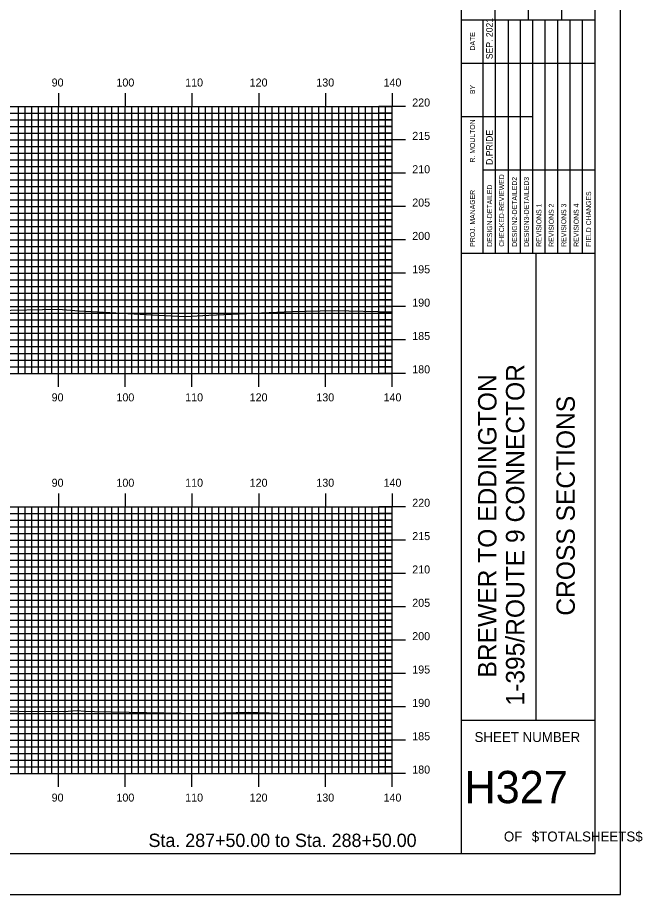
# Model space of a CAD drawing. Extents: x 1812948 to 1813291, y 442591 to 442811.
# Drawn here: x 1813197.3 to 1813291, y 442590.5 to 442722 of the extents above; entities that cross this region are included whole.
import ezdxf

# ---------------------------------------------------------------- set-up
doc = ezdxf.new("R2010")
doc.units = 0
for name, color, linetype in [('BORDER', 7, 'Continuous'), ('H_V ANNOTATION', 7, 'Continuous'), ('MAJOR', 7, 'Continuous'), ('MINOR', 7, 'Continuous'), ('PLOT BOUNDARY', 7, 'Continuous'), ('S_Roadway_Centerline', 7, 'Continuous')]:
    doc.layers.add(name, color=color, linetype=linetype)

msp = doc.modelspace()

# ---------------------------------------------------------------- linework, layer by layer
at = {"layer": 'BORDER'}
for p, q in [((1813263.86, 442596.67), (1813263.86, 442806.67)), ((1813268.86, 442721.67), (1813268.86, 442738.97)), ((1813273.86, 442721.67), (1813273.86, 442738.97)), ((1813278.86, 442721.67), (1813278.86, 442738.97)), ((1813263.86, 442721.67), (1813283.86, 442721.67)), ((1813263.86, 442686.67), (1813283.86, 442686.67)), ((1813275.04, 442616.67), (1813275.04, 442686.67)), ((1813263.86, 442616.67), (1813283.86, 442616.67))]:
    msp.add_line(p, q, dxfattribs=at)
msp.add_lwpolyline([(1812963.86, 442596.67), (1813283.86, 442596.67), (1813283.86, 442806.67), (1812963.86, 442806.67)], close=True, dxfattribs=at)
for points in [[(1813267.08, 442715.17), (1813267.08, 442721.67)], [(1813268.95, 442686.68), (1813268.95, 442721.67)], [(1813270.81, 442721.67), (1813270.81, 442686.68)], [(1813272.68, 442686.68), (1813272.68, 442721.67)], [(1813274.54, 442686.68), (1813274.54, 442721.67)], [(1813276.4, 442686.68), (1813276.4, 442721.67)], [(1813278.27, 442686.68), (1813278.27, 442721.67)], [(1813280.13, 442686.68), (1813280.13, 442721.67)], [(1813281.99, 442686.68), (1813281.99, 442721.67)], [(1813267.09, 442686.68), (1813267.09, 442720.26)], [(1813263.86, 442715.17), (1813283.86, 442715.17)], [(1813263.86, 442707.17), (1813267.09, 442707.17)], [(1813267.08, 442707.17), (1813274.54, 442707.17)], [(1813267.08, 442699.17), (1813283.86, 442699.17)]]:
    msp.add_lwpolyline(points, dxfattribs=at)
at = {"layer": 'MAJOR'}
for p, q in [((1813203.46, 442710.67), (1813203.46, 442708.67)), ((1813213.46, 442710.67), (1813213.46, 442708.67)), ((1813223.46, 442710.67), (1813223.46, 442708.67)), ((1813233.46, 442710.67), (1813233.46, 442708.67)), ((1813243.46, 442710.67), (1813243.46, 442708.67)), ((1813253.46, 442710.67), (1813253.46, 442708.67)), ((1812973.46, 442708.67), (1813253.46, 442708.67)), ((1812973.46, 442708.67), (1813253.46, 442708.67)), ((1813203.46, 442668.67), (1813203.46, 442708.67)), ((1813213.46, 442668.67), (1813213.46, 442708.67)), ((1813223.46, 442668.67), (1813223.46, 442708.67)), ((1813233.46, 442668.67), (1813233.46, 442708.67)), ((1813243.46, 442668.67), (1813243.46, 442708.67)), ((1813255.46, 442708.67), (1813251.45, 442708.67)), ((1813253.46, 442668.67), (1813253.46, 442708.67)), ((1813253.46, 442668.67), (1813253.46, 442708.67)), ((1812973.46, 442703.67), (1813253.46, 442703.67)), ((1813255.46, 442703.67), (1813251.45, 442703.67)), ((1812973.46, 442698.67), (1813253.46, 442698.67)), ((1813255.46, 442698.67), (1813251.45, 442698.67)), ((1812973.46, 442693.67), (1813253.46, 442693.67)), ((1813255.46, 442693.67), (1813251.45, 442693.67)), ((1812973.46, 442688.67), (1813253.46, 442688.67)), ((1813255.46, 442688.67), (1813251.45, 442688.67)), ((1812973.46, 442683.67), (1813253.46, 442683.67)), ((1813255.46, 442683.67), (1813251.45, 442683.67)), ((1812973.46, 442678.67), (1813253.46, 442678.67)), ((1813255.46, 442678.67), (1813251.45, 442678.67)), ((1812973.46, 442673.67), (1813253.46, 442673.67)), ((1813255.46, 442673.67), (1813251.45, 442673.67)), ((1812973.46, 442668.67), (1813253.46, 442668.67)), ((1812973.46, 442668.67), (1813253.46, 442668.67)), ((1813203.46, 442666.66), (1813203.46, 442668.67)), ((1813213.46, 442666.66), (1813213.46, 442668.67)), ((1813223.46, 442666.66), (1813223.46, 442668.67)), ((1813233.46, 442666.66), (1813233.46, 442668.67)), ((1813243.46, 442666.66), (1813243.46, 442668.67)), ((1813255.46, 442668.67), (1813251.45, 442668.67)), ((1813253.46, 442666.66), (1813253.46, 442668.67)), ((1813203.46, 442650.67), (1813203.46, 442648.67)), ((1813213.46, 442650.67), (1813213.46, 442648.67)), ((1813223.46, 442650.67), (1813223.46, 442648.67)), ((1813233.46, 442650.67), (1813233.46, 442648.67)), ((1813243.46, 442650.67), (1813243.46, 442648.67)), ((1813253.46, 442650.67), (1813253.46, 442648.67)), ((1812973.46, 442648.67), (1813253.46, 442648.67)), ((1812973.46, 442648.67), (1813253.46, 442648.67)), ((1813203.46, 442608.67), (1813203.46, 442648.67)), ((1813213.46, 442608.67), (1813213.46, 442648.67)), ((1813223.46, 442608.67), (1813223.46, 442648.67)), ((1813233.46, 442608.67), (1813233.46, 442648.67)), ((1813243.46, 442608.67), (1813243.46, 442648.67)), ((1813255.46, 442648.67), (1813251.45, 442648.67)), ((1813253.46, 442608.67), (1813253.46, 442648.67)), ((1813253.46, 442608.67), (1813253.46, 442648.67)), ((1812973.46, 442643.67), (1813253.46, 442643.67)), ((1813255.46, 442643.67), (1813251.45, 442643.67)), ((1812973.46, 442638.67), (1813253.46, 442638.67)), ((1813255.46, 442638.67), (1813251.45, 442638.67)), ((1812973.46, 442633.67), (1813253.46, 442633.67)), ((1813255.46, 442633.67), (1813251.45, 442633.67)), ((1812973.46, 442628.67), (1813253.46, 442628.67)), ((1813255.46, 442628.67), (1813251.45, 442628.67)), ((1812973.46, 442623.67), (1813253.46, 442623.67)), ((1813255.46, 442623.67), (1813251.45, 442623.67)), ((1812973.46, 442618.67), (1813253.46, 442618.67)), ((1813255.46, 442618.67), (1813251.45, 442618.67)), ((1812973.46, 442613.67), (1813253.46, 442613.67)), ((1813255.46, 442613.67), (1813251.45, 442613.67)), ((1812973.46, 442608.67), (1813253.46, 442608.67)), ((1812973.46, 442608.67), (1813253.46, 442608.67)), ((1813203.46, 442606.66), (1813203.46, 442608.67)), ((1813213.46, 442606.66), (1813213.46, 442608.67)), ((1813223.46, 442606.66), (1813223.46, 442608.67)), ((1813233.46, 442606.66), (1813233.46, 442608.67)), ((1813243.46, 442606.66), (1813243.46, 442608.67)), ((1813255.46, 442608.67), (1813251.45, 442608.67)), ((1813253.46, 442606.66), (1813253.46, 442608.67))]:
    msp.add_line(p, q, dxfattribs=at)
at = {"layer": 'MINOR'}
for p, q in [((1813197.46, 442668.67), (1813197.46, 442708.67)), ((1813198.46, 442668.67), (1813198.46, 442708.67)), ((1813199.46, 442668.67), (1813199.46, 442708.67)), ((1813200.46, 442668.67), (1813200.46, 442708.67)), ((1813201.46, 442668.67), (1813201.46, 442708.67)), ((1813202.46, 442668.67), (1813202.46, 442708.67)), ((1813204.46, 442668.67), (1813204.46, 442708.67)), ((1813205.46, 442668.67), (1813205.46, 442708.67)), ((1813206.46, 442668.67), (1813206.46, 442708.67)), ((1813207.46, 442668.67), (1813207.46, 442708.67)), ((1813208.46, 442668.67), (1813208.46, 442708.67)), ((1813209.46, 442668.67), (1813209.46, 442708.67)), ((1813210.46, 442668.67), (1813210.46, 442708.67)), ((1813211.46, 442668.67), (1813211.46, 442708.67)), ((1813212.46, 442668.67), (1813212.46, 442708.67)), ((1813214.46, 442668.67), (1813214.46, 442708.67)), ((1813215.46, 442668.67), (1813215.46, 442708.67)), ((1813216.46, 442668.67), (1813216.46, 442708.67)), ((1813217.46, 442668.67), (1813217.46, 442708.67)), ((1813218.46, 442668.67), (1813218.46, 442708.67)), ((1813219.46, 442668.67), (1813219.46, 442708.67)), ((1813220.46, 442668.67), (1813220.46, 442708.67)), ((1813221.46, 442668.67), (1813221.46, 442708.67)), ((1813222.46, 442668.67), (1813222.46, 442708.67)), ((1813224.46, 442668.67), (1813224.46, 442708.67)), ((1813225.46, 442668.67), (1813225.46, 442708.67)), ((1813226.46, 442668.67), (1813226.46, 442708.67)), ((1813227.46, 442668.67), (1813227.46, 442708.67)), ((1813228.46, 442668.67), (1813228.46, 442708.67)), ((1813229.46, 442668.67), (1813229.46, 442708.67)), ((1813230.46, 442668.67), (1813230.46, 442708.67)), ((1813231.46, 442668.67), (1813231.46, 442708.67)), ((1813232.46, 442668.67), (1813232.46, 442708.67)), ((1813234.46, 442668.67), (1813234.46, 442708.67)), ((1813235.46, 442668.67), (1813235.46, 442708.67)), ((1813236.46, 442668.67), (1813236.46, 442708.67)), ((1813237.46, 442668.67), (1813237.46, 442708.67)), ((1813238.46, 442668.67), (1813238.46, 442708.67)), ((1813239.46, 442668.67), (1813239.46, 442708.67)), ((1813240.46, 442668.67), (1813240.46, 442708.67)), ((1813241.46, 442668.67), (1813241.46, 442708.67)), ((1813242.46, 442668.67), (1813242.46, 442708.67)), ((1813244.46, 442668.67), (1813244.46, 442708.67)), ((1813245.46, 442668.67), (1813245.46, 442708.67)), ((1813246.46, 442668.67), (1813246.46, 442708.67)), ((1813247.46, 442668.67), (1813247.46, 442708.67)), ((1813248.46, 442668.67), (1813248.46, 442708.67)), ((1813249.46, 442668.67), (1813249.46, 442708.67)), ((1813250.46, 442668.67), (1813250.46, 442708.67)), ((1813251.46, 442668.67), (1813251.46, 442708.67)), ((1813252.46, 442668.67), (1813252.46, 442708.67)), ((1812973.46, 442707.67), (1813253.46, 442707.67)), ((1813253.46, 442707.67), (1813251.45, 442707.67)), ((1812973.46, 442706.67), (1813253.46, 442706.67)), ((1812973.46, 442705.67), (1813253.46, 442705.67)), ((1813253.46, 442706.67), (1813251.45, 442706.67)), ((1813253.46, 442705.67), (1813251.45, 442705.67)), ((1812973.46, 442704.67), (1813253.46, 442704.67)), ((1813253.46, 442704.67), (1813251.45, 442704.67)), ((1812973.46, 442702.67), (1813253.46, 442702.67)), ((1812973.46, 442701.67), (1813253.46, 442701.67)), ((1813253.46, 442702.67), (1813251.45, 442702.67)), ((1813253.46, 442701.67), (1813251.45, 442701.67)), ((1812973.46, 442700.67), (1813253.46, 442700.67)), ((1813253.46, 442700.67), (1813251.45, 442700.67)), ((1812973.46, 442699.67), (1813253.46, 442699.67)), ((1813253.46, 442699.67), (1813251.45, 442699.67)), ((1812973.46, 442697.67), (1813253.46, 442697.67)), ((1813253.46, 442697.67), (1813251.45, 442697.67)), ((1812973.46, 442696.67), (1813253.46, 442696.67)), ((1813253.46, 442696.67), (1813251.45, 442696.67)), ((1812973.46, 442695.67), (1813253.46, 442695.67)), ((1813253.46, 442695.67), (1813251.45, 442695.67)), ((1812973.46, 442694.67), (1813253.46, 442694.67)), ((1813253.46, 442694.67), (1813251.45, 442694.67)), ((1812973.46, 442692.67), (1813253.46, 442692.67)), ((1813253.46, 442692.67), (1813251.45, 442692.67)), ((1812973.46, 442691.67), (1813253.46, 442691.67)), ((1813253.46, 442691.67), (1813251.45, 442691.67)), ((1812973.46, 442690.67), (1813253.46, 442690.67)), ((1813253.46, 442690.67), (1813251.45, 442690.67)), ((1812973.46, 442689.67), (1813253.46, 442689.67)), ((1813253.46, 442689.67), (1813251.45, 442689.67)), ((1812973.46, 442687.67), (1813253.46, 442687.67)), ((1813253.46, 442687.67), (1813251.45, 442687.67)), ((1812973.46, 442686.67), (1813253.46, 442686.67)), ((1813253.46, 442686.67), (1813251.45, 442686.67)), ((1812973.46, 442685.67), (1813253.46, 442685.67)), ((1812973.46, 442684.67), (1813253.46, 442684.67)), ((1813253.46, 442685.67), (1813251.45, 442685.67)), ((1813253.46, 442684.67), (1813251.45, 442684.67)), ((1812973.46, 442682.67), (1813253.46, 442682.67)), ((1813253.46, 442682.67), (1813251.45, 442682.67)), ((1812973.46, 442681.67), (1813253.46, 442681.67)), ((1812973.46, 442680.67), (1813253.46, 442680.67)), ((1813253.46, 442681.67), (1813251.45, 442681.67)), ((1813253.46, 442680.67), (1813251.45, 442680.67)), ((1812973.46, 442679.67), (1813253.46, 442679.67)), ((1813253.46, 442679.67), (1813251.45, 442679.67)), ((1812973.46, 442677.67), (1813253.46, 442677.67)), ((1812973.46, 442676.67), (1813253.46, 442676.67)), ((1813253.46, 442677.67), (1813251.45, 442677.67)), ((1813253.46, 442676.67), (1813251.45, 442676.67)), ((1812973.46, 442675.67), (1813253.46, 442675.67)), ((1813253.46, 442675.67), (1813251.45, 442675.67)), ((1812973.46, 442674.67), (1813253.46, 442674.67)), ((1813253.46, 442674.67), (1813251.45, 442674.67)), ((1812973.46, 442672.67), (1813253.46, 442672.67)), ((1813253.46, 442672.67), (1813251.45, 442672.67)), ((1812973.46, 442671.67), (1813253.46, 442671.67)), ((1813253.46, 442671.67), (1813251.45, 442671.67)), ((1812973.46, 442670.67), (1813253.46, 442670.67)), ((1813253.46, 442670.67), (1813251.45, 442670.67)), ((1812973.46, 442669.67), (1813253.46, 442669.67)), ((1813253.46, 442669.67), (1813251.45, 442669.67)), ((1812973.46, 442647.67), (1813253.46, 442647.67)), ((1813197.46, 442608.67), (1813197.46, 442648.67)), ((1813198.46, 442608.67), (1813198.46, 442648.67)), ((1813199.46, 442608.67), (1813199.46, 442648.67)), ((1813200.46, 442608.67), (1813200.46, 442648.67)), ((1813201.46, 442608.67), (1813201.46, 442648.67)), ((1813202.46, 442608.67), (1813202.46, 442648.67)), ((1813204.46, 442608.67), (1813204.46, 442648.67)), ((1813205.46, 442608.67), (1813205.46, 442648.67)), ((1813206.46, 442608.67), (1813206.46, 442648.67)), ((1813207.46, 442608.67), (1813207.46, 442648.67)), ((1813208.46, 442608.67), (1813208.46, 442648.67)), ((1813209.46, 442608.67), (1813209.46, 442648.67)), ((1813210.46, 442608.67), (1813210.46, 442648.67)), ((1813211.46, 442608.67), (1813211.46, 442648.67)), ((1813212.46, 442608.67), (1813212.46, 442648.67)), ((1813214.46, 442608.67), (1813214.46, 442648.67)), ((1813215.46, 442608.67), (1813215.46, 442648.67)), ((1813216.46, 442608.67), (1813216.46, 442648.67)), ((1813217.46, 442608.67), (1813217.46, 442648.67)), ((1813218.46, 442608.67), (1813218.46, 442648.67)), ((1813219.46, 442608.67), (1813219.46, 442648.67)), ((1813220.46, 442608.67), (1813220.46, 442648.67)), ((1813221.46, 442608.67), (1813221.46, 442648.67)), ((1813222.46, 442608.67), (1813222.46, 442648.67)), ((1813224.46, 442608.67), (1813224.46, 442648.67)), ((1813225.46, 442608.67), (1813225.46, 442648.67)), ((1813226.46, 442608.67), (1813226.46, 442648.67)), ((1813227.46, 442608.67), (1813227.46, 442648.67)), ((1813228.46, 442608.67), (1813228.46, 442648.67)), ((1813229.46, 442608.67), (1813229.46, 442648.67)), ((1813230.46, 442608.67), (1813230.46, 442648.67)), ((1813231.46, 442608.67), (1813231.46, 442648.67)), ((1813232.46, 442608.67), (1813232.46, 442648.67)), ((1813234.46, 442608.67), (1813234.46, 442648.67)), ((1813235.46, 442608.67), (1813235.46, 442648.67)), ((1813236.46, 442608.67), (1813236.46, 442648.67)), ((1813237.46, 442608.67), (1813237.46, 442648.67)), ((1813238.46, 442608.67), (1813238.46, 442648.67)), ((1813239.46, 442608.67), (1813239.46, 442648.67)), ((1813240.46, 442608.67), (1813240.46, 442648.67)), ((1813241.46, 442608.67), (1813241.46, 442648.67)), ((1813242.46, 442608.67), (1813242.46, 442648.67)), ((1813244.46, 442608.67), (1813244.46, 442648.67)), ((1813245.46, 442608.67), (1813245.46, 442648.67)), ((1813246.46, 442608.67), (1813246.46, 442648.67)), ((1813247.46, 442608.67), (1813247.46, 442648.67)), ((1813248.46, 442608.67), (1813248.46, 442648.67)), ((1813249.46, 442608.67), (1813249.46, 442648.67)), ((1813250.46, 442608.67), (1813250.46, 442648.67)), ((1813253.46, 442647.67), (1813251.45, 442647.67)), ((1813251.46, 442608.67), (1813251.46, 442648.67)), ((1813252.46, 442608.67), (1813252.46, 442648.67)), ((1812973.46, 442646.67), (1813253.46, 442646.67)), ((1813253.46, 442646.67), (1813251.45, 442646.67)), ((1812973.46, 442645.67), (1813253.46, 442645.67)), ((1813253.46, 442645.67), (1813251.45, 442645.67)), ((1812973.46, 442644.67), (1813253.46, 442644.67)), ((1813253.46, 442644.67), (1813251.45, 442644.67)), ((1812973.46, 442642.67), (1813253.46, 442642.67)), ((1813253.46, 442642.67), (1813251.45, 442642.67)), ((1812973.46, 442641.67), (1813253.46, 442641.67)), ((1813253.46, 442641.67), (1813251.45, 442641.67)), ((1812973.46, 442640.67), (1813253.46, 442640.67)), ((1813253.46, 442640.67), (1813251.45, 442640.67)), ((1812973.46, 442639.67), (1813253.46, 442639.67)), ((1813253.46, 442639.67), (1813251.45, 442639.67)), ((1812973.46, 442637.67), (1813253.46, 442637.67)), ((1813253.46, 442637.67), (1813251.45, 442637.67)), ((1812973.46, 442636.67), (1813253.46, 442636.67)), ((1813253.46, 442636.67), (1813251.45, 442636.67)), ((1812973.46, 442635.67), (1813253.46, 442635.67)), ((1812973.46, 442634.67), (1813253.46, 442634.67)), ((1813253.46, 442635.67), (1813251.45, 442635.67)), ((1813253.46, 442634.67), (1813251.45, 442634.67)), ((1812973.46, 442632.67), (1813253.46, 442632.67)), ((1813253.46, 442632.67), (1813251.45, 442632.67)), ((1812973.46, 442631.67), (1813253.46, 442631.67)), ((1812973.46, 442630.67), (1813253.46, 442630.67)), ((1813253.46, 442631.67), (1813251.45, 442631.67)), ((1813253.46, 442630.67), (1813251.45, 442630.67)), ((1812973.46, 442629.67), (1813253.46, 442629.67)), ((1813253.46, 442629.67), (1813251.45, 442629.67)), ((1812973.46, 442627.67), (1813253.46, 442627.67)), ((1812973.46, 442626.67), (1813253.46, 442626.67)), ((1813253.46, 442627.67), (1813251.45, 442627.67)), ((1813253.46, 442626.67), (1813251.45, 442626.67)), ((1812973.46, 442625.67), (1813253.46, 442625.67)), ((1813253.46, 442625.67), (1813251.45, 442625.67)), ((1812973.46, 442624.67), (1813253.46, 442624.67)), ((1813253.46, 442624.67), (1813251.45, 442624.67)), ((1812973.46, 442622.67), (1813253.46, 442622.67)), ((1813253.46, 442622.67), (1813251.45, 442622.67)), ((1812973.46, 442621.67), (1813253.46, 442621.67)), ((1813253.46, 442621.67), (1813251.45, 442621.67)), ((1812973.46, 442620.67), (1813253.46, 442620.67)), ((1813253.46, 442620.67), (1813251.45, 442620.67)), ((1812973.46, 442619.67), (1813253.46, 442619.67)), ((1813253.46, 442619.67), (1813251.45, 442619.67)), ((1812973.46, 442617.67), (1813253.46, 442617.67)), ((1813253.46, 442617.67), (1813251.45, 442617.67)), ((1812973.46, 442616.67), (1813253.46, 442616.67)), ((1813253.46, 442616.67), (1813251.45, 442616.67)), ((1812973.46, 442615.67), (1813253.46, 442615.67)), ((1813253.46, 442615.67), (1813251.45, 442615.67)), ((1812973.46, 442614.67), (1813253.46, 442614.67)), ((1813253.46, 442614.67), (1813251.45, 442614.67)), ((1812973.46, 442612.67), (1813253.46, 442612.67)), ((1813253.46, 442612.67), (1813251.45, 442612.67)), ((1812973.46, 442611.67), (1813253.46, 442611.67)), ((1813253.46, 442611.67), (1813251.45, 442611.67)), ((1812973.46, 442610.67), (1813253.46, 442610.67)), ((1812973.46, 442609.67), (1813253.46, 442609.67)), ((1813253.46, 442610.67), (1813251.45, 442610.67)), ((1813253.46, 442609.67), (1813251.45, 442609.67))]:
    msp.add_line(p, q, dxfattribs=at)
at = {"layer": 'PLOT BOUNDARY'}
msp.add_lwpolyline([(1812947.67, 442590.55), (1813287.67, 442590.55), (1813287.67, 442810.55), (1812947.67, 442810.55)], close=True, dxfattribs=at)
at = {"layer": 'S_Roadway_Centerline'}
for points in [[(1813193.92, 442678.09), (1813203.41, 442678.28), (1813206.56, 442678.02), (1813218.45, 442677.39), (1813222.46, 442677.19), (1813226, 442677.4), (1813238.43, 442677.95), (1813244.8, 442678.08), (1813253.46, 442677.88)], [(1813084.84, 442620.64), (1813088.36, 442620.5), (1813089.18, 442620.47), (1813090.73, 442620.43), (1813105.15, 442620.24), (1813112.48, 442620.04), (1813122.27, 442620.01), (1813139.78, 442619.7), (1813140.48, 442619.66), (1813141.1, 442619.66), (1813142.38, 442619.6), (1813168.45, 442618.61), (1813174.52, 442618.21), (1813185.03, 442618.05), (1813190.81, 442618.09), (1813204.22, 442618), (1813206.3, 442618.12), (1813207.36, 442618.02), (1813208.86, 442617.96), (1813224.42, 442617.68), (1813231.94, 442617.86), (1813241.21, 442617.57), (1813253.46, 442617.74)]]:
    msp.add_lwpolyline(points, dxfattribs=at)

# ---------------------------------------------------------------- texts
at = {"layer": 'BORDER'}
for s, height, p in [('SEP. 2021', 0.969, (1813268.5, 442715.76)), ('DATE', 0.743, (1813265.86, 442717.08)), ('BY', 0.743, (1813265.86, 442710.54)), ('R. MOULTON', 0.745, (1813265.86, 442700.28)), ('D.PRIDE', 0.969, (1813268.5, 442699.92)), ('CHECKED-REVIEWED', 0.7455, (1813270.22, 442687.65)), ('DESIGN2-DETAILED2', 0.7455, (1813272.16, 442687.65)), ('DESIGN3-DETAILED3', 0.7455, (1813273.94, 442687.65)), ('DESIGN-DETAILED', 0.7455, (1813268.43, 442687.65)), ('PROJ. MANAGER', 0.7455, (1813265.86, 442687.65)), ('FIELD CHANGES', 0.7455, (1813283.26, 442687.65)), ('REVISIONS 1', 0.7455, (1813275.81, 442687.65)), ('REVISIONS 2', 0.7455, (1813277.67, 442687.65)), ('REVISIONS 3', 0.7455, (1813279.53, 442687.65)), ('REVISIONS 4', 0.7455, (1813281.4, 442687.65)), ('1-395/ROUTE 9 CONNECTOR', 2.7557, (1813273.26, 442618.87)), ('BREWER TO EDDINGTON', 2.7557, (1813269.08, 442623.07)), ('CROSS SECTIONS', 2.7557, (1813280.82, 442632.34))]:
    msp.add_text(s, height=height, rotation=90, dxfattribs=at).set_placement(p)
for s, height, p in [('SHEET NUMBER', 1.4905, (1813265.79, 442613.4)), ('H327', 4.839, (1813264.29, 442604.23)), ('OF', 1.491, (1813270.19, 442598.49)), ('$TOTALSHEETS$', 1.4905, (1813274.37, 442598.49))]:
    msp.add_text(s, height=height, dxfattribs=at).set_placement(p)
at = {"layer": 'H_V ANNOTATION'}
for s, height, p in [('90', 1.2, (1813202.43, 442711.67)), ('100', 1.2, (1813212.14, 442711.67)), ('110', 1.2, (1813222.44, 442711.67)), ('120', 1.2, (1813232.1, 442711.67)), ('130', 1.2, (1813242.09, 442711.67)), ('140', 1.2, (1813252.16, 442711.67)), ('220', 1.2, (1813256.46, 442708.67)), ('215', 1.2, (1813256.46, 442703.67)), ('210', 1.2, (1813256.46, 442698.67)), ('205', 1.2, (1813256.46, 442693.67)), ('200', 1.2, (1813256.46, 442688.67)), ('195', 1.2, (1813256.46, 442683.67)), ('190', 1.2, (1813256.46, 442678.67)), ('185', 1.2, (1813256.46, 442673.67)), ('180', 1.2, (1813256.46, 442668.67)), ('90', 1.2, (1813202.43, 442664.47)), ('100', 1.2, (1813212.14, 442664.47)), ('110', 1.2, (1813222.44, 442664.47)), ('120', 1.2, (1813232.1, 442664.47)), ('130', 1.2, (1813242.09, 442664.47)), ('140', 1.2, (1813252.16, 442664.47)), ('90', 1.2, (1813202.43, 442651.67)), ('100', 1.2, (1813212.14, 442651.67)), ('110', 1.2, (1813222.44, 442651.67)), ('120', 1.2, (1813232.1, 442651.67)), ('130', 1.2, (1813242.09, 442651.67)), ('140', 1.2, (1813252.16, 442651.67)), ('220', 1.2, (1813256.46, 442648.67)), ('215', 1.2, (1813256.46, 442643.67)), ('210', 1.2, (1813256.46, 442638.67)), ('205', 1.2, (1813256.46, 442633.67)), ('200', 1.2, (1813256.46, 442628.67)), ('195', 1.2, (1813256.46, 442623.67)), ('190', 1.2, (1813256.46, 442618.67)), ('185', 1.2, (1813256.46, 442613.67)), ('180', 1.2, (1813256.46, 442608.67)), ('90', 1.2, (1813202.43, 442604.47)), ('100', 1.2, (1813212.14, 442604.47)), ('110', 1.2, (1813222.44, 442604.47)), ('120', 1.2, (1813232.1, 442604.47)), ('130', 1.2, (1813242.09, 442604.47)), ('140', 1.2, (1813252.16, 442604.47)), ('Sta. 287+50.00 to Sta. 288+50.00', 2.0004, (1813216.95, 442597.66))]:
    msp.add_text(s, height=height, dxfattribs=at).set_placement(p)

doc.saveas('drawing.dxf')
